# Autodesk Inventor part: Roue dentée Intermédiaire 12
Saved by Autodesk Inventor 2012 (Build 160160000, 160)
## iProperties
Created: 2013-08
Part Number: Roue dentée Intermédiaire 12
Material: Default
Document SubType Name: Modeling
Designer: hilarion
Density: 1 g/cm^3
Author: Balduini Gael & Faure Olivier
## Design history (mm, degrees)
node "Roue dentée Intermédiaire 121"
node "Roue dentée Intermédiaire 12"
node "Roue dentée Intermédiaire 12_1"
node "Base1"
node "Base2"
